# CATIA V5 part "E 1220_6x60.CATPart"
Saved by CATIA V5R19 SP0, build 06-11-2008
Part number: E 1220_6x60
Definition: E 1220_6x60
Nomenclature: E 1220_6x60
Source: Unknown
Description: PART--DESC
Bounding box of the stored display mesh (mm): x 19 to 31, y -6 to 6, z -49.45 to 10.55
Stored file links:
  C:\Users\jsmid\Desktop\DP_Smidak_Forma LEGO\E 1220_6x60.CATPart
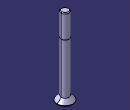
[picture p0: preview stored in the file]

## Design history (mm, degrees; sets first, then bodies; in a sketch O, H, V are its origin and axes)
Body1 "E 1220_6x60" (main body)
  Solid1: solid without history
